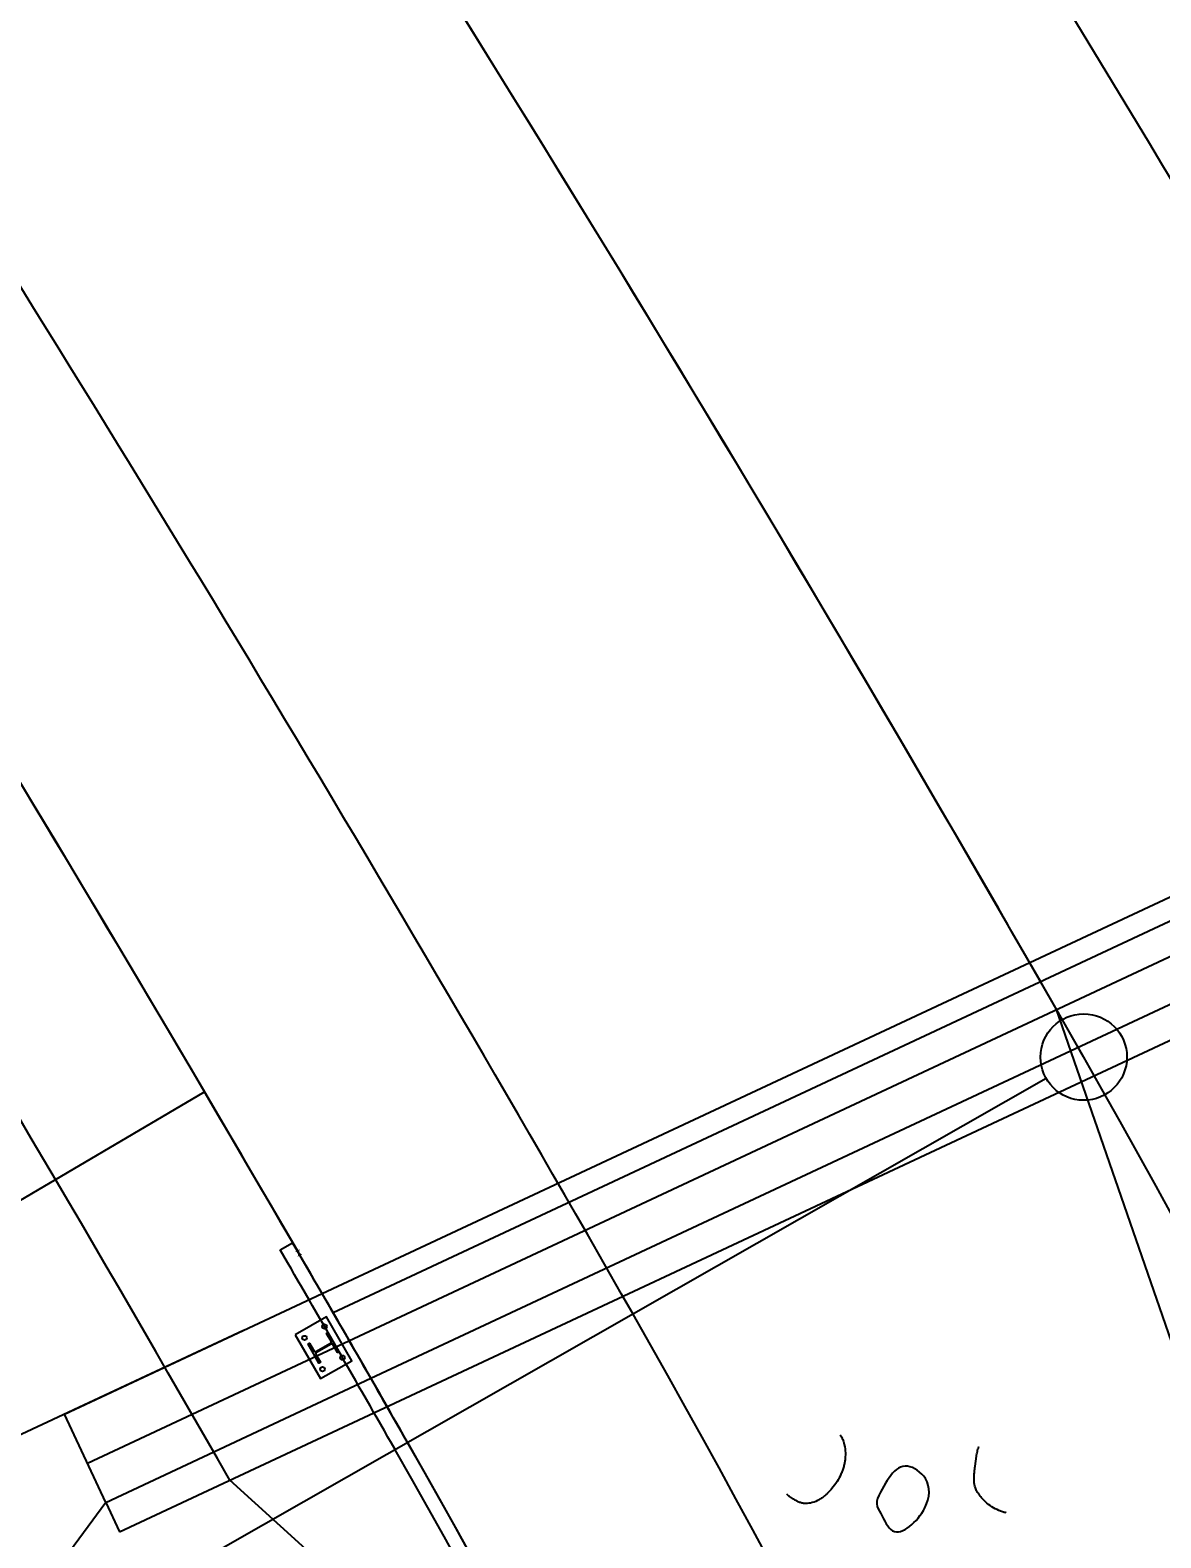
# Model space of a CAD drawing. Extents: x 2355002 to 2355569, y 708374 to 709566.
# Drawn here: x 2355304.53 to 2355330.68, y 709344.57 to 709379.45 of the extents above; entities that cross this region are included whole.
import ezdxf

# ---------------------------------------------------------------- set-up
doc = ezdxf.new("R2010")
doc.units = 0
for name, color, linetype in [('BD_X_Building', 7, 'Continuous'), ('BR_X_Brg_Centerline', 7, 'Continuous'), ('BR_X_Det_Centerline', 7, 'Continuous'), ('BR_X_Gen_Approach_Slab', 7, 'Continuous'), ('BR_X_Rail_Stl_Det', 7, 'Continuous'), ('BR_X_Slab_Object', 7, 'Continuous'), ('DR_X_Cells', 7, 'Continuous'), ('DR_X_Underdrain', 7, 'Continuous'), ('DT_X_Slope_Break_Line', 7, 'Continuous'), ('GK_Drainage_Nodes', 7, 'Continuous'), ('PM_X_CL_Double_Solid', 7, 'Continuous'), ('PM_X_Edge_Line', 7, 'Continuous'), ('PM_X_Stop_Line', 7, 'Continuous'), ('RD_X_GR_Lt', 7, 'Continuous'), ('RD_X_Wall', 7, 'Continuous'), ('SH_Text', 7, 'Continuous'), ('VG_X_Cells', 7, 'Continuous'), ('VG_X_Tree_Line_Rt', 7, 'Continuous')]:
    doc.layers.add(name, color=color, linetype=linetype)

msp = doc.modelspace()

# ---------------------------------------------------------------- linework, layer by layer
at = {"layer": 'BR_X_Brg_Centerline'}
msp.add_line((2355305.852, 709346.301), (2355355.213, 709369.404), dxfattribs=at)
at = {"layer": 'BR_X_Det_Centerline'}
msp.add_line((2355360.141, 709264.65), (2355328.268, 709356.793), dxfattribs=at)
at = {"layer": 'BR_X_Gen_Approach_Slab'}
msp.add_line((2355311.533, 709349.788), (2355344.252, 709365.102), dxfattribs=at)
for radius, start, end in [(736.472, 29.735627, 32.069293), (700.472, 29.975428, 32.430394)]:
    msp.add_arc((2354704.756, 708999.812), radius, start, end, dxfattribs=at)
at = {"layer": 'BR_X_Rail_Stl_Det'}
msp.add_line((2355310.311, 709351.235), (2355310.599, 709351.402), dxfattribs=at)
for points in [[(2355310.66, 709349.268), (2355311.242, 709348.257), (2355311.964, 709348.672), (2355311.382, 709349.684), (2355310.66, 709349.268)], [(2355311.488, 709349.121), (2355311.383, 709349.303), (2355311.416, 709349.322), (2355311.669, 709348.883), (2355311.636, 709348.864), (2355311.531, 709349.046)], [(2355311.081, 709348.838), (2355310.955, 709349.057), (2355310.988, 709349.076), (2355311.093, 709348.894)], [(2355311.136, 709348.819), (2355311.241, 709348.637), (2355311.208, 709348.618), (2355311.081, 709348.838)], [(2355311.134, 709348.883), (2355311.477, 709349.081)], [(2355311.49, 709349.057), (2355311.147, 709348.86)]]:
    msp.add_lwpolyline(points, dxfattribs=at)
for centre in [(2355311.334, 709349.464), (2355310.874, 709349.199), (2355311.75, 709348.742), (2355311.289, 709348.476)]:
    msp.add_circle(centre, 0.0521, dxfattribs=at)
for centre, radius, start, end in [((2354704.756, 708999.812), 700.139, 29.692057, 30.127945), ((2354704.756, 708999.812), 700.472, 29.692057, 30.127945), ((2355311.119, 709348.909), 0.0298, 209.9241, 299.9241), ((2355311.162, 709348.834), 0.0298, 119.9241, 209.9241), ((2355311.462, 709349.106), 0.0298, 299.9241, 29.9241), ((2355311.505, 709349.032), 0.0298, 29.9241, 119.9241), ((2355104.75, 709227.887), 240.024, 6.23645, 29.69194), ((2355104.75, 709227.887), 239.69, 6.23645, 29.69194)]:
    msp.add_arc(centre, radius, start, end, dxfattribs=at)
at = {"layer": 'BR_X_Slab_Object'}
for centre, radius, start, end in [((2354704.756, 708999.812), 700.472, 29.692057, 29.975428), ((2355104.75, 709227.887), 240.024, 6.69347, 29.69206)]:
    msp.add_arc(centre, radius, start, end, dxfattribs=at)
at = {"layer": 'DR_X_Cells'}
for p, q in [((2355305.322, 709347.434), (2355311.282, 709350.223)), ((2355306.276, 709345.396), (2355312.408, 709348.266)), ((2355306.276, 709345.396), (2355305.322, 709347.434))]:
    msp.add_line(p, q, dxfattribs=at)
at = {"layer": 'DR_X_Underdrain'}
msp.add_line((2355303.391, 709351.847), (2355308.563, 709354.888), dxfattribs=at)
at = {"layer": 'DT_X_Slope_Break_Line'}
msp.add_line((2355309.464, 709349.372), (2355302.456, 709346.092), dxfattribs=at)
at = {"layer": 'GK_Drainage_Nodes'}
for p, q in [((2355306.594, 709344.716), (2355355.955, 709367.819)), ((2355306.276, 709345.396), (2355306.594, 709344.716))]:
    msp.add_line(p, q, dxfattribs=at)
at = {"layer": 'PM_X_CL_Double_Solid'}
for centre, radius, start, end in [((2354704.755, 708999.811), 718.474, 29.692057, 41.655322), ((2354704.755, 708999.811), 718.474, 29.69174, 36.439187), ((2355104.75, 709227.886), 258.024, 5.4603, 29.69206), ((2355104.75, 709227.886), 258.024, 5.4603, 29.69206)]:
    msp.add_arc(centre, radius, start, end, dxfattribs=at)
at = {"layer": 'PM_X_Edge_Line'}
for centre, radius, start, end in [((2354704.744, 708999.831), 730.474, 29.689927, 32.450085), ((2354704.744, 708999.831), 706.474, 29.689927, 32.450025), ((2355104.75, 709227.886), 246.024, 5.4603, 29.69206)]:
    msp.add_arc(centre, radius, start, end, dxfattribs=at)
at = {"layer": 'PM_X_Stop_Line'}
msp.add_lwpolyline([(2355306.276, 709345.396), (2355290.879, 709324.489), (2355296.582, 709319.103), (2355311.362, 709334.527), (2355360.724, 709357.63), (2355392.727, 709358.151), (2355391.331, 709364.068), (2355355.637, 709368.498)], dxfattribs=at)
for points in [[(2355323.265, 709346.96), (2355323.29, 709346.915), (2355323.311, 709346.869), (2355323.345, 709346.776), (2355323.38, 709346.589), (2355323.378, 709346.404), (2355323.365, 709346.314), (2355323.355, 709346.27), (2355323.344, 709346.227), (2355323.315, 709346.136), (2355323.281, 709346.048), (2355323.191, 709345.877), (2355323.072, 709345.714), (2355323, 709345.636), (2355322.961, 709345.597), (2355322.941, 709345.578), (2355322.92, 709345.559), (2355322.886, 709345.53), (2355322.85, 709345.503), (2355322.775, 709345.455), (2355322.616, 709345.39), (2355322.456, 709345.37), (2355322.379, 709345.379), (2355322.343, 709345.389), (2355322.307, 709345.403), (2355322.234, 709345.439), (2355322.163, 709345.481), (2355322.094, 709345.529), (2355322.028, 709345.584)], [(2355327.099, 709345.153), (2355327.016, 709345.176), (2355326.933, 709345.208), (2355326.77, 709345.294), (2355326.617, 709345.413), (2355326.547, 709345.484), (2355326.513, 709345.523), (2355326.497, 709345.543), (2355326.489, 709345.553), (2355326.481, 709345.564), (2355326.452, 709345.605), (2355326.428, 709345.646), (2355326.392, 709345.728), (2355326.36, 709345.893), (2355326.364, 709346.057), (2355326.373, 709346.139), (2355326.383, 709346.221), (2355326.397, 709346.338), (2355326.413, 709346.456), (2355326.436, 709346.573), (2355326.47, 709346.687), (2355326.471, 709346.689)], [(2355324.123, 709345.482), (2355324.82, 709346.233), (2355325.233, 709345.944), (2355325.22, 709345.27), (2355324.476, 709344.736), (2355324.202, 709345.137), (2355324.107, 709345.36), (2355324.123, 709345.482)]]:
    msp.add_spline(points, degree=3, dxfattribs=at)
at = {"layer": 'RD_X_GR_Lt'}
msp.add_arc((2354704.755, 708999.811), 700.474, 30.105407, 41.655322, dxfattribs=at)
at = {"layer": 'RD_X_Wall'}
msp.add_circle((2355328.895, 709355.695), 1, dxfattribs=at)
for centre, radius, start, end in [((2354704.755, 708999.811), 718.474, 29.692057, 41.655322), ((2355104.75, 709227.886), 258.024, 5.4603, 29.69206)]:
    msp.add_arc(centre, radius, start, end, dxfattribs=at)
at = {"layer": 'SH_Text'}
msp.add_line((2355328.027, 709355.2), (2355266.135, 709319.909), dxfattribs=at)
at = {"layer": 'VG_X_Cells'}
for p, q in [((2355311.283, 709350.223), (2355344.003, 709365.537)), ((2355312.408, 709348.266), (2355345.119, 709363.576))]:
    msp.add_line(p, q, dxfattribs=at)
at = {"layer": 'VG_X_Tree_Line_Rt'}
msp.add_line((2355318.172, 709337.714), (2355309.147, 709345.912), dxfattribs=at)
msp.add_arc((2354704.756, 708999.812), 696.472, 29.797214, 32.804787, dxfattribs=at)

# ---------------------------------------------------------------- texts
at = {"layer": 'BD_X_Building'}
msp.add_text('X', height=0.14, rotation=25.0808, dxfattribs=at).set_placement((2355310.712, 709351.075))
msp.add_text('X', height=0.14, rotation=25.0808, dxfattribs=at).set_placement((2355310.712, 709351.075))

doc.saveas('drawing.dxf')
